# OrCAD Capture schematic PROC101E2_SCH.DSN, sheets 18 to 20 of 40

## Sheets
18 27. HSE CONNECTOR: size C; title: HSE CONNECTOR
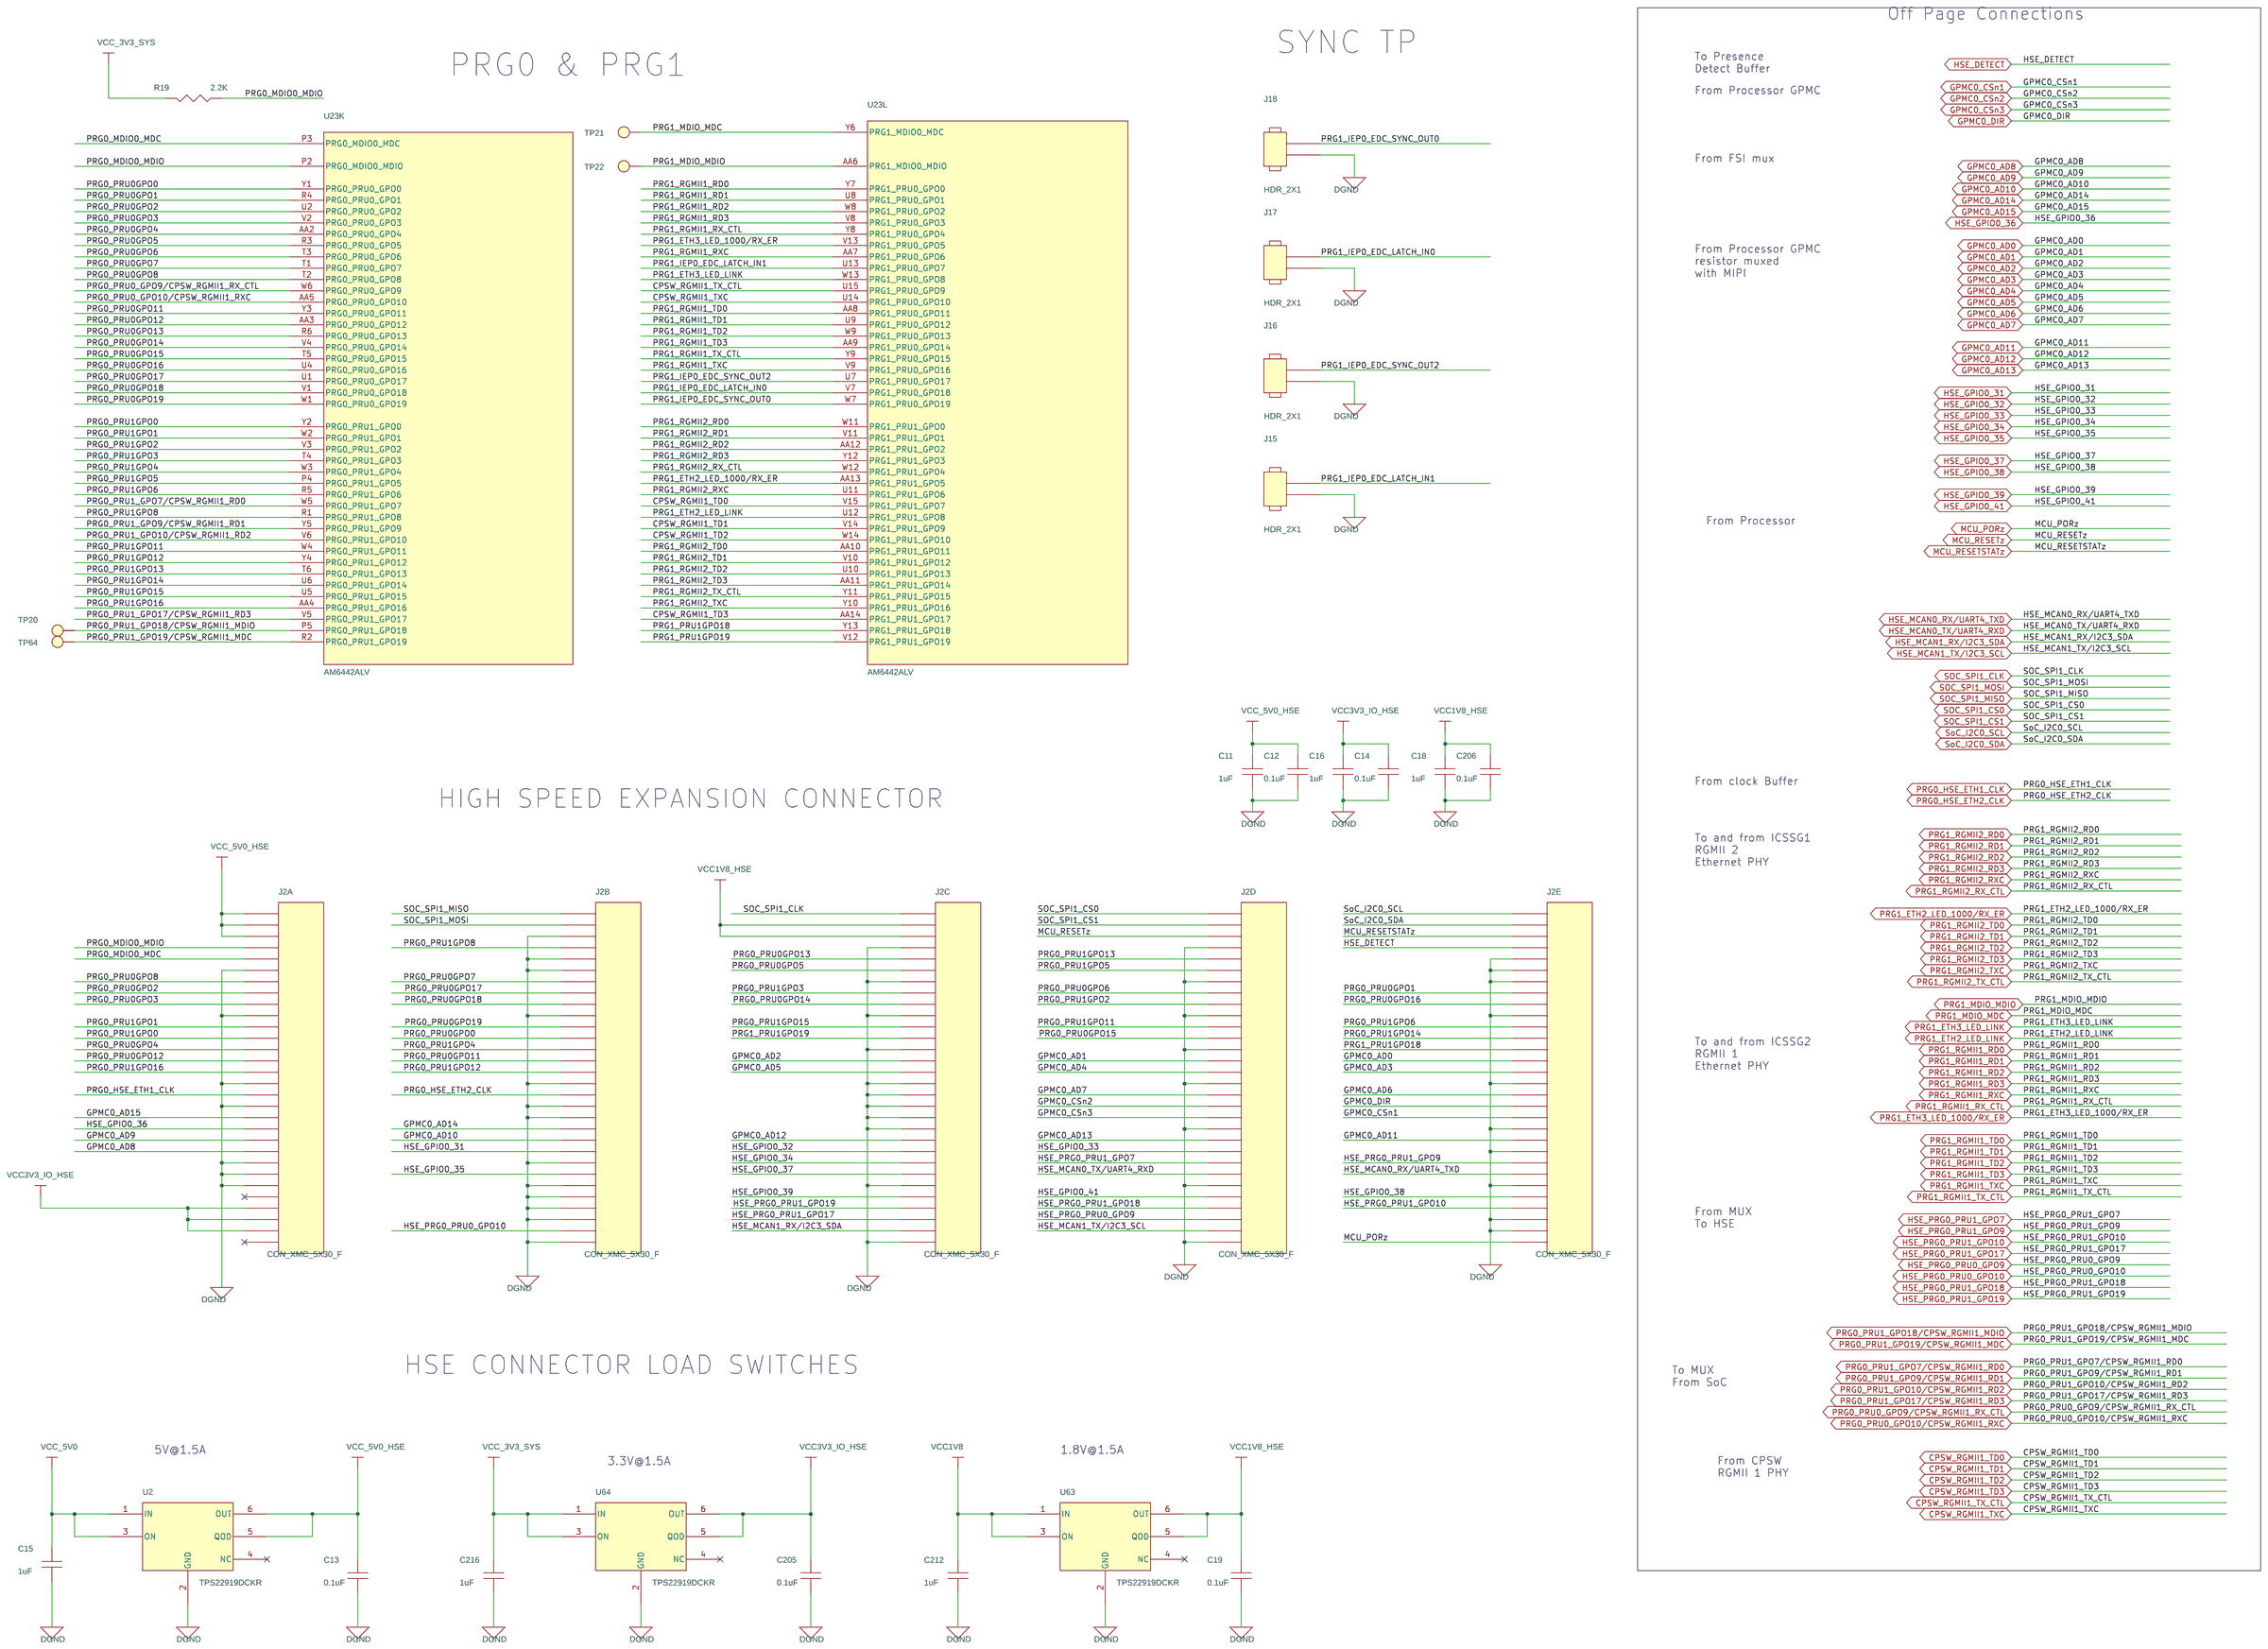
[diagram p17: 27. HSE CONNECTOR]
19 28.GPMC & FSI CONNECTOR: size C; title: GPMC
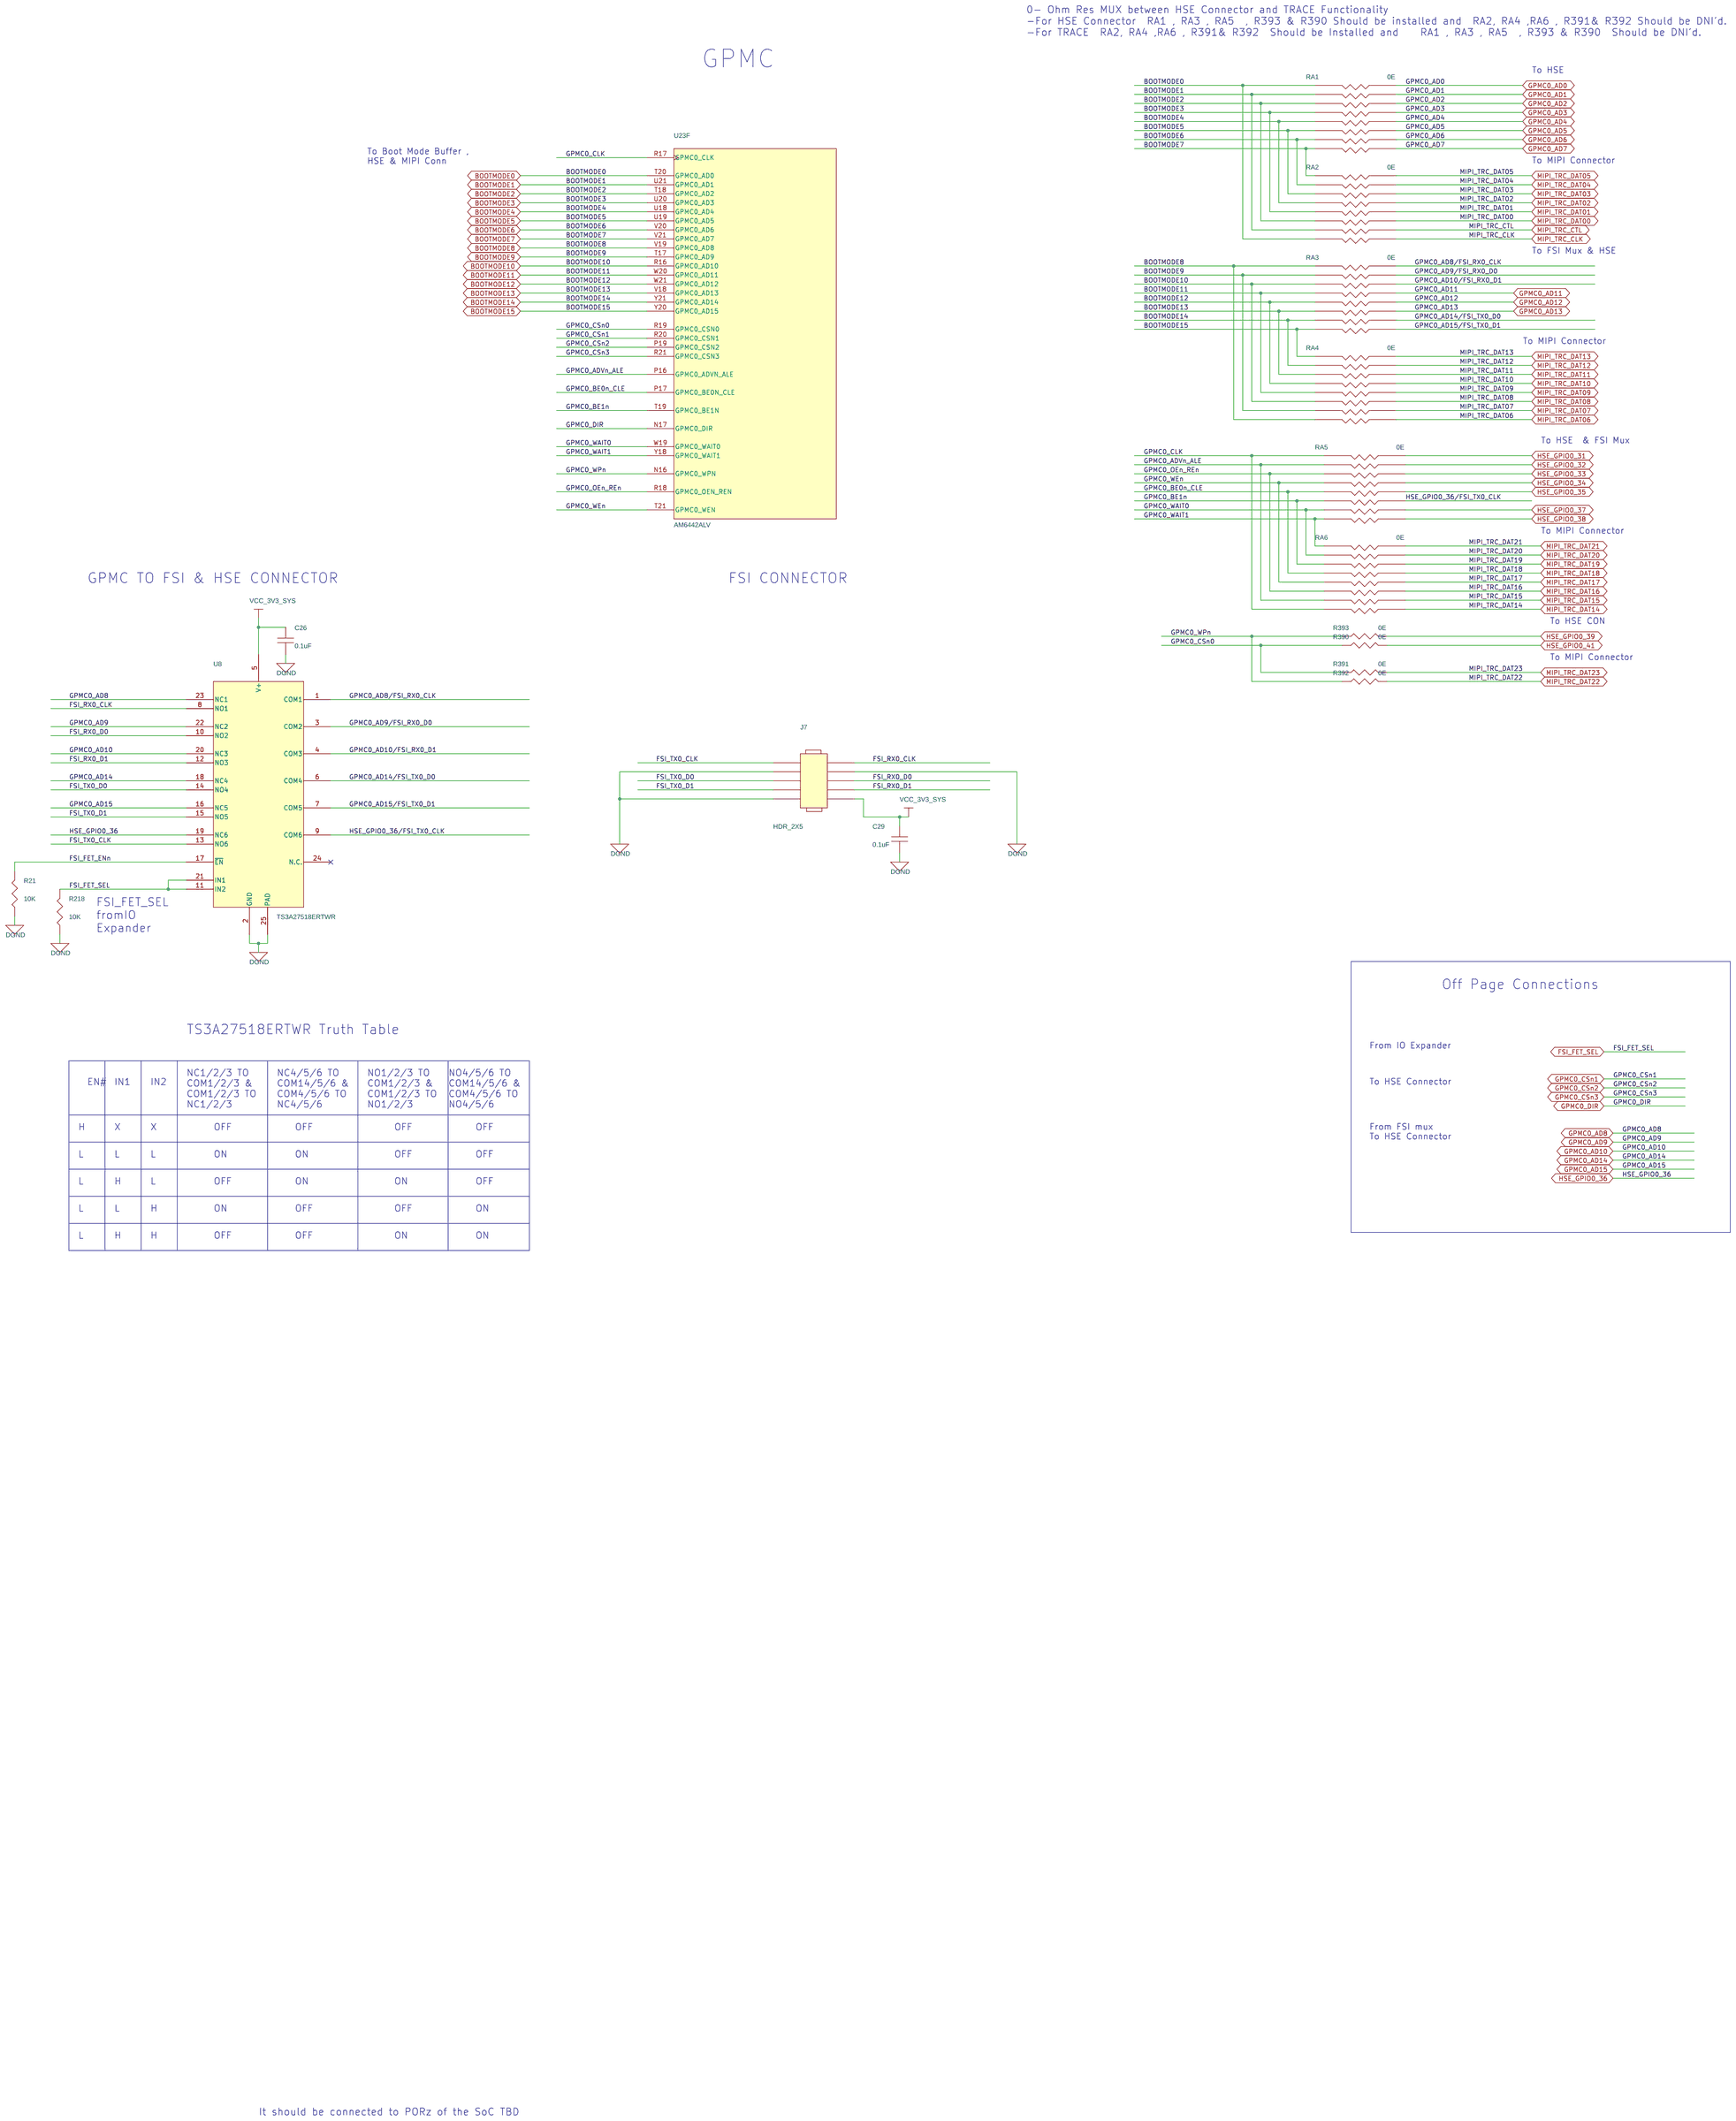
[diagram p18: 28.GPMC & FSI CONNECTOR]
20 25.USB2.0 INTERFACE: size C; title: USB 2.0 INTERFACE
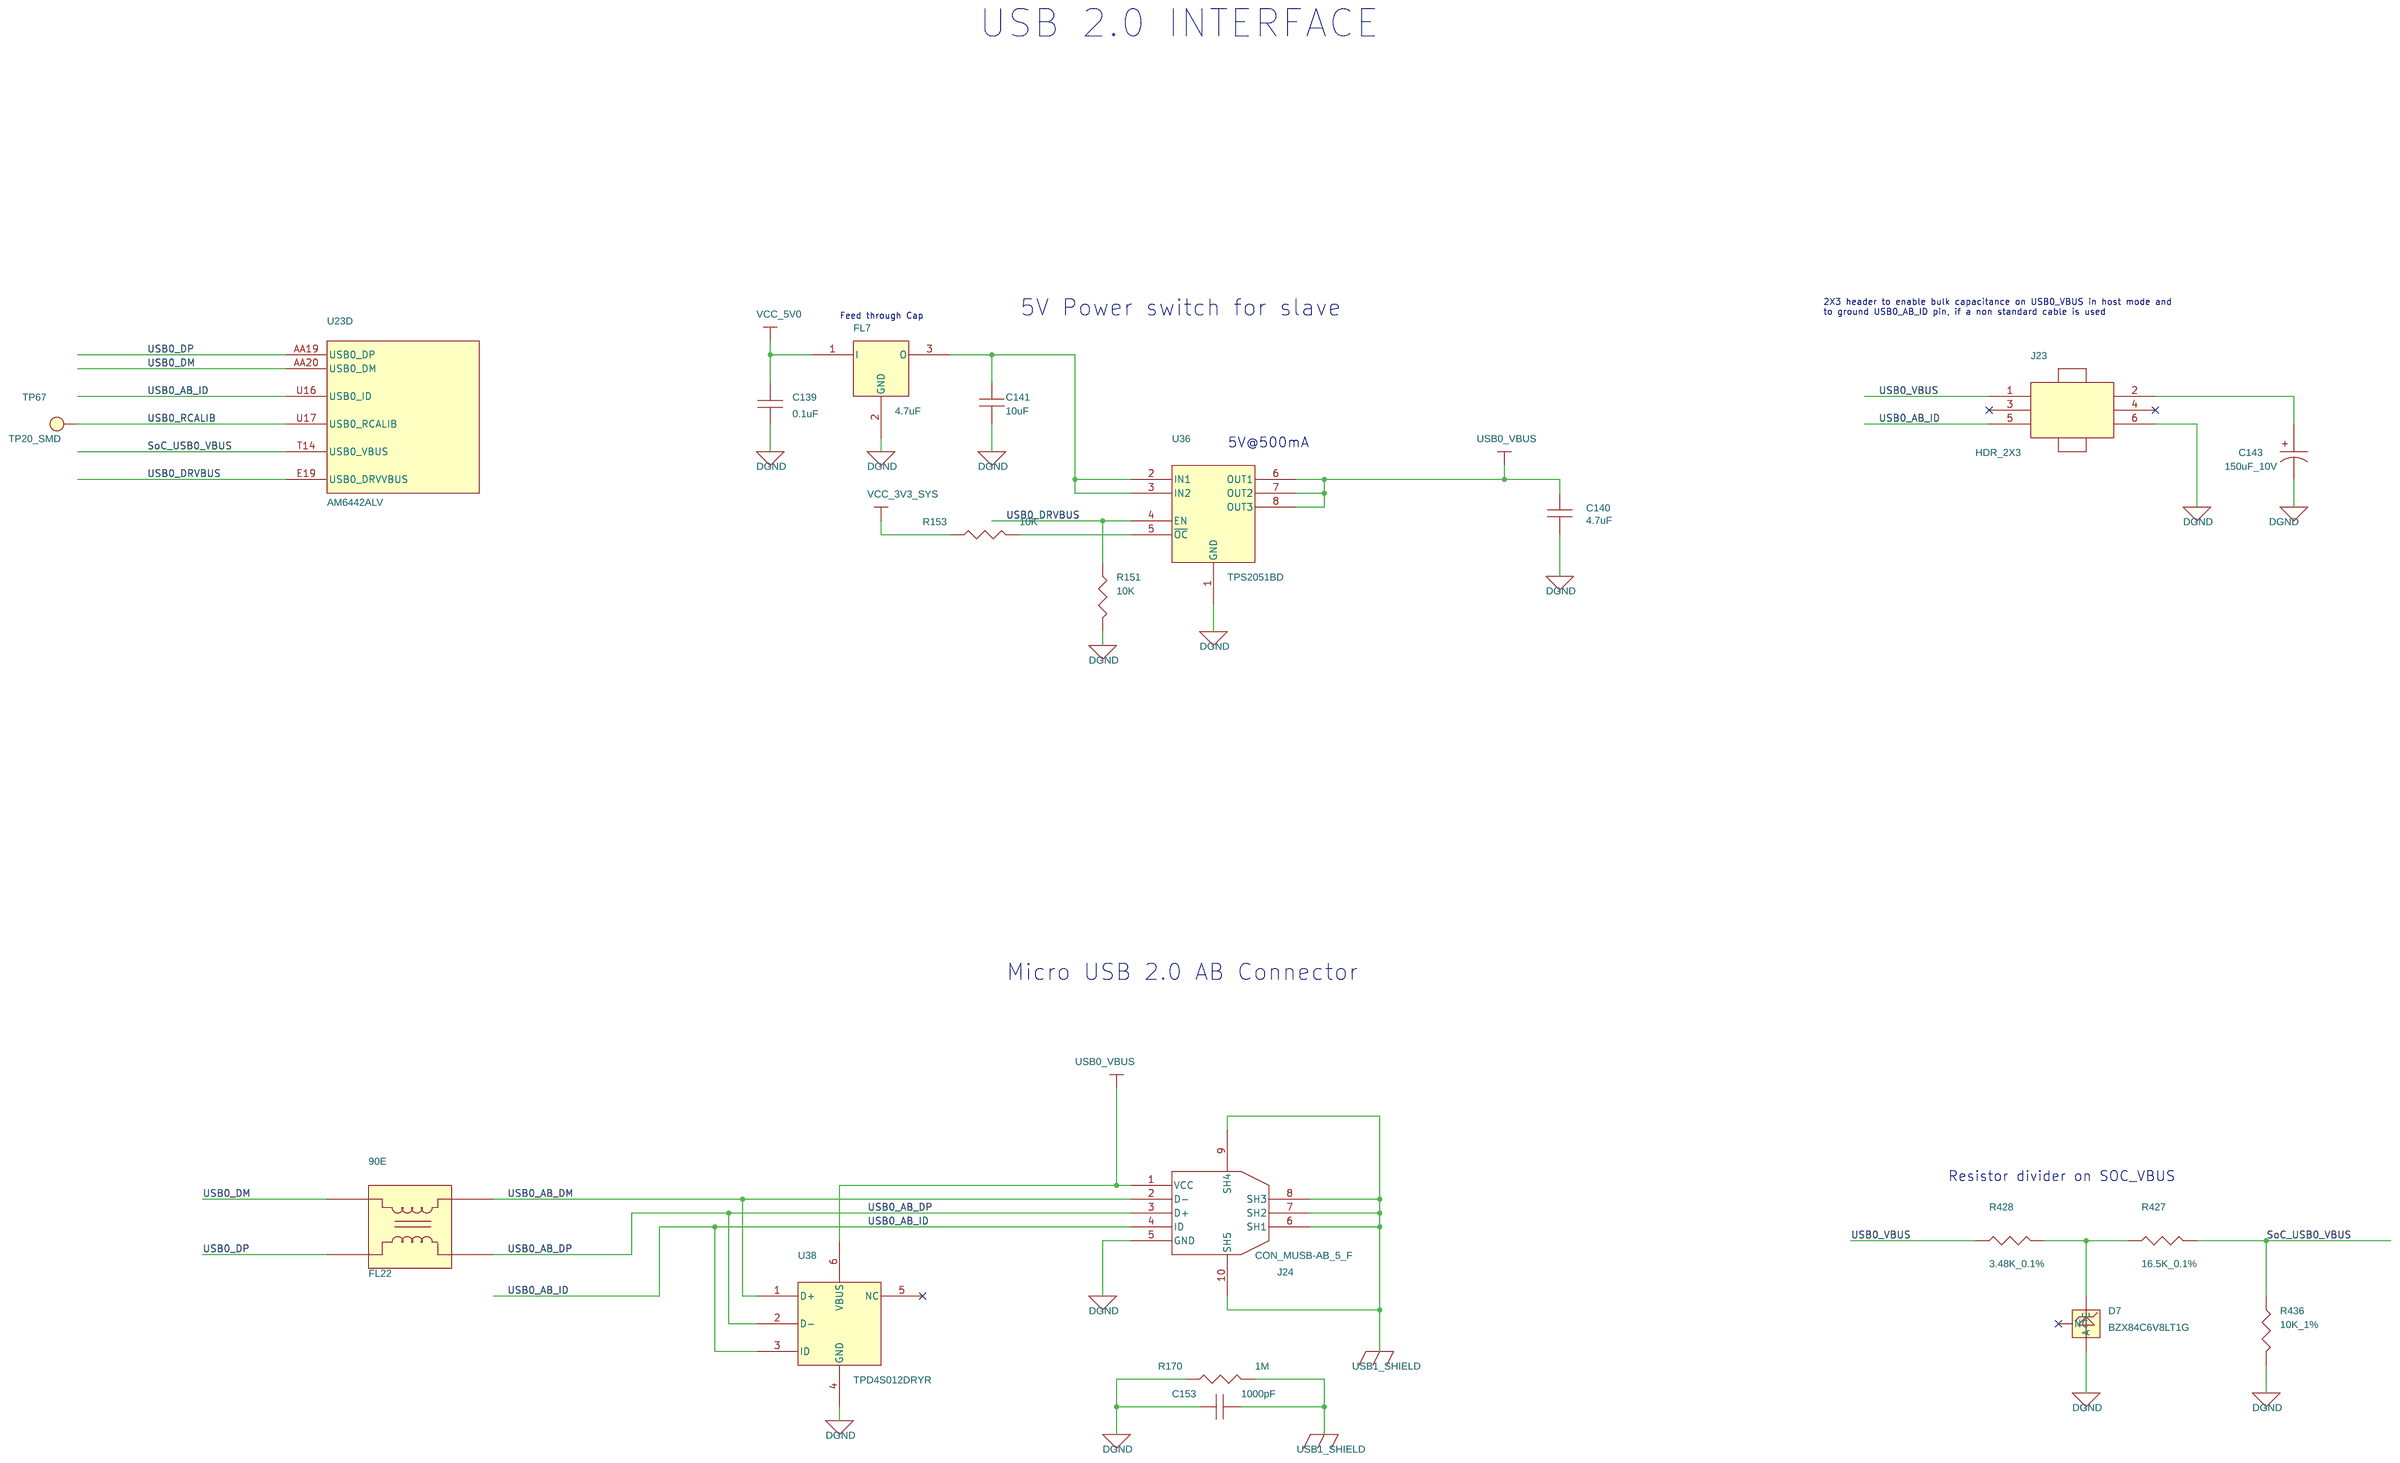
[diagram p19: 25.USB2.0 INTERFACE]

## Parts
sheet 11.SOC VSS
U23  AM6442ALV  [FCBGA441_31-49_680X680_2-6]  (sections A,B,C,D,E,F,G,H,I,J,K,L,M,N,O,P)
sheet 25.USB2.0 INTERFACE
C139  0.1uF  [CAP0402_0-75]
C140  4.7uF  [CAP0402_0-75]
C141  10uF  [CAP0402_0-75]
C143  150uF_10V  [CAPT7343D_3-25]
C153  1000pF  [CAP1206_1-75]
D7  BZX84C6V8LT1G  [SOT23-123_1-2]
FL7  4.7uF  [EMIFIL_NFM21P_0805_1]
FL22  90E  [IND4_ACM2012_90X50_SMD_1-3]
J23  HDR_2X3  [HDR_2X3_TSW-103-07-D_S_T_8-4]
J24  CON_MUSB-AB_5_F  [CON_USBAB5_ZX62RD-AB-5P8_S_R_S_3-2]
R151  10K  [RES0402_0-5]
R153  10K  [RES0402_0-5]
R170  1M  [RES0603_0-75]
R427  16.5K_0.1%  [RES0402_0-5]
R428  3.48K_0.1%  [RES0402_0-5]
R436  10K_1%  [RES0402_0-5]
TP67  TP20_SMD  [TP20_SMD]
U36  TPS2051BD  [SOIC8_1-8]
U38  TPD4S012DRYR  [SON6_SN74LVC2G17_40X60_0-6]
sheet 27. HSE CONNECTOR
C11  1uF  [CAP0402_0-75]
C12  0.1uF  [CAP0402_0-75]
C13  0.1uF  [CAP0402_0-75]
C14  0.1uF  [CAP0402_0-75]
C15  1uF  [CAP0402_0-75]
C16  1uF  [CAP0402_0-75]
C18  1uF  [CAP0402_0-75]
C19  0.1uF  [CAP0402_0-75]
C205  0.1uF  [CAP0402_0-75]
C206  0.1uF  [CAP0402_0-75]
C212  1uF  [CAP0402_0-75]
C216  1uF  [CAP0402_0-75]
J2  CON_XMC_5X30_F  [CON_XMC5X30_SEAF-30-06-05-2-A_S_S_S_6-4]  (sections A,B,C,D,E)
J15  HDR_2X1  [HDR_2X1_100_S_T]
J16  HDR_2X1  [HDR_2X1_100_S_T]
J17  HDR_2X1  [HDR_2X1_100_S_T]
J18  HDR_2X1  [HDR_2X1_100_S_T]
R19  2.2K  [RES0402_0-5]
TP20  TP20_SMD  [TP20_SMD]
TP21  TP20_SMD  [TP20_SMD]
TP22  TP20_SMD  [TP20_SMD]
TP64  TP20_SMD  [TP20_SMD]
U2  TPS22919DCKR  [SC70-6_1-1]
U63  TPS22919DCKR  [SC70-6_1-1]
U64  TPS22919DCKR  [SC70-6_1-1]
sheet 28.GPMC & FSI CONNECTOR
C26  0.1uF  [CAP0402_0-75]
C29  0.1uF  [CAP0402_0-75]
J7  HDR_2X5  [HDR_5X2_100_S_T_8-6]
R21  10K  [RES0402_0-5]
R218  10K  [RES0402_0-5]
R390  0E  [RES0402_0-5]
R391  0E  [RES0402_0-5]
R392  0E  [RES0402_0-5]
R393  0E  [RES0402_0-5]
RA1  0E  [RESA_EXB2HV_0602-8_0-6]
RA2  0E  [RESA_EXB2HV_0602-8_0-6]
RA3  0E  [RESA_EXB2HV_0602-8_0-6]
RA4  0E  [RESA_EXB2HV_0602-8_0-6]
RA5  0E  [RESA_EXB2HV_0602-8_0-6]
RA6  0E  [RESA_EXB2HV_0602-8_0-6]
U8  TS3A27518ERTWR  [QFN24_19-68_160X160_0-8]

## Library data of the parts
U23 = AM64-SVB_BGA441: IC AM64 SoC MICROPROCESSOR BGA441; Chkd/date: MANIRAJA/020520; Crtd /date: ALVY/090420; Custom_Duty: 15%; Customs_HS_Code: 85423100; Distributor_name: NA; Distributor_part_number: NA; Footprint Path: Y:\MIS_DATABASE\Library\ALTIUM_TOOL\PCB_FOOTPRINTS\Altium_Footprint_Lib.PcbLib; Height: 2.57MM; Library Path: Y:\MIS_DATABASE\Library\ALTIUM_TOOL\SCHEMATICS_PARTS\MS_MICROPROCESSOR_Library.schlib; Mfr_name: TEXAS INSTRUMENTS; Mfr_part_number: AM6442ASFGGAALV; Mistral Part No: 141220040002; Package: BGA441; Part_type: ICS\DIGITAL\MICROPROCESSOR; Project: AM64x_SVB BRD; RoHS: NA; Temperature: NA; Tolerance: NA; Voltage: NA; Wattage: NA; Weight: NA; Datasheet: Y:\MIS_DATABASE\DATASHEETS\ICS\DIGITAL\MICROCONTROLLER\AM64-SoC_SVB.PDF
C12-C14 C19 C26 C29 C139 C205 C206 = CAP: CAP CERAMIC 0.1uF 25V 20% X5R 0402; Alt_Mfr_name: YAGEO AMERICA; Alt_Mfr_part_number: CC0402KRX5R8BB104; Chkd/date: MANIRAJA/170820; Crtd /date: ALVY/170820; Custom_Duty: 15%; Customs_HS_Code: 85322990; Distributor_name: DIGIKEY; Distributor_part_number: 732-7495-1-ND; Footprint Path: Y:\MIS_DATABASE\Library\ALTIUM_TOOL\PCB_FOOTPRINTS\Altium_Footprint_Lib.PcbLib; Height: 0.55MM; Library Path: Y:\MIS_DATABASE\Library\ALTIUM_TOOL\SCHEMATICS_PARTS\MS_DISCRETE_Library.schlib; Mfr_name: WURTH ELECTRONICS; Mfr_part_number: 885012105018; Mistral Part No: 120020080003-R; Package: 0402; Part_type: CAPACITORS\CERAMIC; Project: AM64x_EVM_BRD; RoHS: RoHS; Temperature: -55°C+85°C; Tolerance: 20%; Voltage: 25V; Wattage: NA; Weight: 0.65mg; Datasheet: Y:\MIS_DATABASE\DATASHEETS\CAPACITORS\885012105018.PDF
C140 = CAP: CAP CERAMIC 4.7uF 10V 20% X5R 0402; Chkd/date: MANIRAJA/230118; Crtd /date: MANIRAJA/230118; Custom_Duty: 15%; Customs_HS_Code: 85322990; Distributor_name: DIGIKEY; Distributor_part_number: 478-10791-1-ND; Footprint Path: Y:\MIS_DATABASE\Library\ALTIUM_TOOL\PCB_FOOTPRINTS\Altium_Footprint_Lib.PcbLib; Height: 0.71MM; Library Path: Y:\MIS_DATABASE\Library\ALTIUM_TOOL\SCHEMATICS_PARTS\MS_DISCRETE_Library.schlib; Mfr_name: AVX CORPORATION; Mfr_part_number: 0402ZD475MAT2A; Mistral Part No: 120012060002-R; Package: 0402; Part_type: CAPACITORS\CERAMIC; Project: TI_MAXIE_CPB; RoHS: RoHS; Temperature: -55°C+85°C; Tolerance: 20%; Voltage: 10V; Wattage: NA; Weight: 0.65mg; Datasheet: Y:\MIS_DATABASE\DATASHEETS\CAPACITORS\AVX_MLC.PDF
C141 = CAP: CAP CERAMIC 10uF 10V 20% X5R 0402; Chkd/date: MANIRAJA/300520; Crtd /date: ALVY/260520; Custom_Duty: 15%; Customs_HS_Code: 85322990; Distributor_name: DIGIKEY; Distributor_part_number: 490-GRM155R61A106ME11DTR-ND; Footprint Path: Y:\MIS_DATABASE\Library\ALTIUM_TOOL\PCB_FOOTPRINTS\Altium_Footprint_Lib.PcbLib; Height: 0.55MM; Library Path: Y:\MIS_DATABASE\Library\ALTIUM_TOOL\SCHEMATICS_PARTS\MS_DISCRETE_Library.schlib; Mfr_name: MURATA; Mfr_part_number: GRM155R61A106ME11D; Mistral Part No: 120013110019-R; Package: 0402; Part_type: CAPACITORS\CERAMIC; Project: QCS610_NANOSOM; RoHS: RoHS; Temperature: -55°C+85°C; Tolerance: 20%; Voltage: 10V; Wattage: NA; Weight: 3.1mg; Datasheet: Y:\MIS_DATABASE\DATASHEETS\CAPACITORS\MURATA-GXX-SER_NOV17.PDF
C143 = CAP_POL: CAP TANTALUM 150uF 10V 10% ESR 0.9E D7343; Chkd/date: MANIRAJA/240118; Crtd /date: MANIRAJA/240118; Custom_Duty: 15%; Customs_HS_Code: 85322990; Distributor_name: DIGIKEY; Distributor_part_number: 478-11241-1-ND; Footprint Path: Y:\MIS_DATABASE\Library\ALTIUM_TOOL\PCB_FOOTPRINTS\Altium_Footprint_Lib.PcbLib; Height: 3.10MM; Library Path: Y:\MIS_DATABASE\Library\ALTIUM_TOOL\SCHEMATICS_PARTS\MS_DISCRETE_Library.schlib; Mfr_name: AVX CORPORATION; Mfr_part_number: TAJD157K010TNJV; Mistral Part No: 120018010025-R; Package: D7343; Part_type: CAPACITORS\TANTALUM; Project: TI_MAXIE_CPB; RoHS: RoHS; Temperature: -55°C+125°C; Tolerance: 10%; Voltage: 10V; Wattage: NA; Weight: 670mg; Datasheet: Y:\MIS_DATABASE\DATASHEETS\CAPACITORS\AVX-TAJ-SER.PDF
C153 = CAP: CAP CERAMIC 1000pF 2KV 10% X7R 1206; Chkd/date: SHREESHAIL/291106; Crtd /date: MAZHAR/281106; Custom_Duty: 15%; Customs_HS_Code: 85322990; Distributor_name: DIGIKEY; Distributor_part_number: 478-2956-1-ND; Footprint Path: Y:\MIS_DATABASE\Library\ALTIUM_TOOL\PCB_FOOTPRINTS\Altium_Footprint_Lib.PcbLib; Height: 1.52MM; Library Path: Y:\MIS_DATABASE\Library\ALTIUM_TOOL\SCHEMATICS_PARTS\MS_DISCRETE_Library.schlib; Mfr_name: AVX CORPORATION; Mfr_part_number: 1206GC102KAT1A; Mistral Part No: 120015080006-R; Package: 1206; Part_type: CAPACITORS\CERAMIC; Project: ADR1B; RoHS: RoHS; Temperature: -55°C+125°C; Tolerance: 10%; Voltage: 2KV; Wattage: NA; Weight: 16.2mg; Datasheet: Y:\MIS_DATABASE\DATASHEETS\CAPACITORS\AVX_HV-MLC.PDF
D7 = DIODE_ZENER_SOT23_13: DIODE ZENER 250mW 6.8V SOT23-123; Chkd/date: MANIRAJA/031017; Crtd /date: MANIRAJA/031017; Custom_Duty: 15%; Customs_HS_Code: 85412900; Distributor_name: DIGIKEY; Distributor_part_number: BZX84C6V8LT1GOSCT-ND; Height: 1.11MM; Mfr_name: ON SEMICONDUCTOR; Mistral Part No: 130017100002-R; Package: SOT23-123; Part_type: DIODE\ZENER; Project: TI_MAXIE_CPB; RoHS: RoHS; Temperature: -65°C+150°C; Tolerance: NA; Voltage: 6.8V; Wattage: NA; Weight: 8mg; Datasheet: Y:\MIS_DATABASE\DATASHEETS\DISCRETES\DIODES\BZX84XX.PDF
FL7 = EMI_FILTER: PASSIVE FILTER EMI 4.7uF 0805-3; Chkd/date: VASANTHA/191216; Crtd /date: USMAN/200409; Custom_Duty: 24%; Customs_HS_Code: 85437099; Distributor_name: NA; Distributor_part_number: NA; Height: 0.95MM; Mfr_name: MURATA; Mfr_part_number: NFM21PC475B1A3; Mistral Part No: 130009060011; Package: 0805; Part_type: FILTER; Project: AXON; Temperature: -40°C+85°C; Tolerance: NA; Voltage: NA; Wattage: NA; Weight: NA; Datasheet: Y:\MIS_DATABASE\DATASHEETS\DISCRETES\INDUCTORS\NFM21P.PDF
FL22 = EMIFILTER_ACM: PASSIVE FILTER COMMON MODE 90E 400mA SMD; Chkd/date: MANIRAJA/130218; Crtd /date: MAZHAR/270907; Custom_Duty: 24%; Customs_HS_Code: 85437099; Distributor_name: DIGIKEY; Distributor_part_number: 445-2207-1-ND; Height: 1.30MM; Mfr_name: TDK CORPORATION; Mfr_part_number: ACM2012-900-2P-T002; Mistral Part No: 130009030803-R; Package: SMD; Part_type: FILTER; Project: SMART VIEW_NVR; RoHS: RoHS; Temperature: -40°C+85°C; Tolerance: NA; Voltage: NA; Wattage: NA; Weight: 5.5mg; Datasheet: Y:\MIS_DATABASE\DATASHEETS\ICS\MISC\ACM2012-SER.PDF
J23 = HEADER_3X2: CON HDR 2X3 2.54MM PITCH ST TH; Chkd/date: MANIRAJA/230118; Crtd /date: MANIRAJA/220118; Custom_Duty: 24%; Customs_HS_Code: 85369090; Distributor_name: DIGIKEY; Distributor_part_number: SAM1034-03-ND; Height: 8.38MM; Mfr_name: SAMTEC; Mfr_part_number: TSW-103-07-T-D; Mistral Part No: 150018010019-R; Package: THRU-HOLE; Part_type: CONNECTOR\HEADERS; Project: TI_MAXIE_CPB; RoHS: RoHS; Temperature: -55°C+105°C; Tolerance: NA; Voltage: NA; Wattage: NA; Weight: NA; Datasheet: Y:\MIS_DATABASE\DATASHEETS\CONNECTORS\TSW-MK.PDF
J24 = CON_USB_MINI-AB_10: CON MICRO USB-AB TYPE 5POS FEMALE RT SMD; Chkd/date: MANIRAJA/150620; Crtd /date: MUDDU/090410; Custom_Duty: 24%; Customs_HS_Code: 85369090; Distributor_name: DIGIKEY; Distributor_part_number: H125777CT-ND; Footprint Path: Y:\MIS_DATABASE\Library\ALTIUM_TOOL\PCB_FOOTPRINTS\Altium_Footprint_Lib.PcbLib; Height: 3.15MM; Library Path: Y:\MIS_DATABASE\Library\ALTIUM_TOOL\SCHEMATICS_PARTS\MS_CONNECTOR_Library.schlib; Mfr_name: HRS; Mfr_part_number: ZX62RD-AB-5P8(30); Mistral Part No: 150010040003-R; Package: SMD; Part_type: CONNECTOR\USB; Project: ESEE; RoHS: RoHS; Temperature: -30°C+85°C; Tolerance: NA; Voltage: NA; Wattage: NA; Weight: NA; Datasheet: Y:\MIS_DATABASE\DATASHEETS\CONNECTORS\ZX62RD-AB-5P8.PDF
R21 R151 R153 R218 = RESISTOR: RES 10K 1/16W 5% 0402; Chkd/date: VASANTHA/061216; Crtd /date: MAZHAR/230805; Custom_Duty: 15%; Customs_HS_Code: 85332119; Distributor_name: DIGIKEY; Distributor_part_number: 311-10KJRCT-ND; Footprint Path: Y:\MIS_DATABASE\Library\ALTIUM_TOOL\PCB_FOOTPRINTS\Altium_Footprint_Lib.PcbLib; Height: 0.40MM; Library Path: Y:\MIS_DATABASE\Library\ALTIUM_TOOL\SCHEMATICS_PARTS\MS_DISCRETE_Library.schlib; Mfr_name: YAGEO AMERICA; Mfr_part_number: RC0402JR-0710KL; Mistral Part No: 110011060021-R; Package: 0402; Part_type: RESISTORS\FIXED; Project: HSE; RoHS: RoHS; Temperature: -55°C+155°C; Tolerance: 5%; Voltage: NA; Wattage: 1/16W; Weight: 0.65mg; Datasheet: Y:\MIS_DATABASE\DATASHEETS\RESISTORS\RCXXXXL-SER_MAR18.PDF
R170 = RESISTOR: RES 1M 1/10W 5% 0603; Chkd/date: VASANTHA/060217; Crtd /date: USMAN/111207; Custom_Duty: 15%; Customs_HS_Code: 85332119; Distributor_name: DIGIKEY; Distributor_part_number: P1.0MGCT-ND; Footprint Path: Y:\MIS_DATABASE\Library\ALTIUM_TOOL\PCB_FOOTPRINTS\Altium_Footprint_Lib.PcbLib; Height: 0.55MM; Library Path: Y:\MIS_DATABASE\Library\ALTIUM_TOOL\SCHEMATICS_PARTS\MS_DISCRETE_Library.schlib; Mfr_name: PANASONIC-ECG; Mfr_part_number: ERJ-3GEYJ105V; Mistral Part No: 110009030413-R; Package: 0603; Part_type: RESISTORS\FIXED; Project: BSN; RoHS: RoHS; Temperature: -55°C+155°C; Tolerance: 5%; Voltage: NA; Wattage: 1/10W; Weight: 2mg; Datasheet: Y:\MIS_DATABASE\DATASHEETS\RESISTORS\PAN-ERJSER_NOV17.PDF
R427 = RESISTOR: RES 16.5K 1/16W 0.1% 0402; Chkd/date: MANIRAJA/051018; Crtd /date: ALVY/051018; Custom_Duty: 15%; Customs_HS_Code: 85332119; Distributor_name: DIGIKEY; Distributor_part_number: P16.5KDCCT-ND; Footprint Path: Y:\MIS_DATABASE\Library\ALTIUM_TOOL\PCB_FOOTPRINTS\Altium_Footprint_Lib.PcbLib; Height: 0.40MM; Library Path: Y:\MIS_DATABASE\Library\ALTIUM_TOOL\SCHEMATICS_PARTS\MS_DISCRETE_Library.schlib; Mfr_name: PANASONIC-ECG; Mfr_part_number: ERA-2AEB1652X; Mistral Part No: 110018100006-R; Package: 0402; Part_type: RESISTORS\FIXED; Project: TI_J7_SVB-DUT; RoHS: RoHS; Temperature: -55°C+155°C; Tolerance: 0.1%; Voltage: NA; Wattage: 1/16W; Weight: 0.6mg; Datasheet: Y:\MIS_DATABASE\DATASHEETS\RESISTORS\ERA-1A.PDF
R428 = RESISTOR: RES 3.48K 1/16W 0.1% 0402; Chkd/date: MANIRAJA/051018; Crtd /date: ALVY/051018; Custom_Duty: 15%; Customs_HS_Code: 85332119; Distributor_name: DIGIKEY; Distributor_part_number: P3.48KDCCT-ND; Footprint Path: Y:\MIS_DATABASE\Library\ALTIUM_TOOL\PCB_FOOTPRINTS\Altium_Footprint_Lib.PcbLib; Height: 0.40MM; Library Path: Y:\MIS_DATABASE\Library\ALTIUM_TOOL\SCHEMATICS_PARTS\MS_DISCRETE_Library.schlib; Mfr_name: PANASONIC-ECG; Mfr_part_number: ERA-2AEB3481X; Mistral Part No: 110018100005-R; Package: 0402; Part_type: RESISTORS\FIXED; Project: TI_J7_SVB-DUT; RoHS: RoHS; Temperature: -55°C+155°C; Tolerance: 0.1%; Voltage: NA; Wattage: 1/16W; Weight: 0.6mg; Datasheet: Y:\MIS_DATABASE\DATASHEETS\RESISTORS\ERA-1A.PDF
R436 = RESISTOR: RES 10K 1/16W 1% 0402; Chkd/date: VASANTHA/201216; Crtd /date: GEETHA/290506; Custom_Duty: 15%; Customs_HS_Code: 85332119; Distributor_name: DIGIKEY; Distributor_part_number: 311-10.0KLRTR-ND; Footprint Path: Y:\MIS_DATABASE\Library\ALTIUM_TOOL\PCB_FOOTPRINTS\Altium_Footprint_Lib.PcbLib; Height: 0.40MM; Library Path: Y:\MIS_DATABASE\Library\ALTIUM_TOOL\SCHEMATICS_PARTS\MS_DISCRETE_Library.schlib; Mfr_name: YAGEO AMERICA; Mfr_part_number: RC0402FR-0710KL; Mistral Part No: 110015090015-R; Package: 0402; Part_type: RESISTORS\FIXED; Project: VOCERA; RoHS: RoHS; Temperature: -55°C+155°C; Tolerance: 1%; Voltage: NA; Wattage: 1/16W; Weight: 0.65mg; Datasheet: Y:\MIS_DATABASE\DATASHEETS\RESISTORS\RCXXXXL-SER_MAR18.PDF
TP20-TP22 TP64 TP67 = TESTPOINT: TESTPOINT CIR 20 SMD; Chkd/date: SHREESHAIL/171006; Crtd /date: MAZHAR/171006; Custom_Duty: NA; Customs_HS_Code: NA; Distributor_name: NA; Distributor_part_number: NA; Footprint Path: Y:\MIS_DATABASE\Library\ALTIUM_TOOL\PCB_FOOTPRINTS\Altium_Footprint_Lib.PcbLib; Height: NA; Library Path: Y:\MIS_DATABASE\Library\ALTIUM_TOOL\SCHEMATICS_PARTS\MS_DISCRETE_Library.schlib; MECHANICAL 3D STEP FILE: NA; Mfr_name: LOCAL; Mistral Part No: NA; Package: SMD; Project: BT MODULE_CSRBC04; RoHS: NA; Temperature: NA; Tolerance: NA; Voltage: NA; Wattage: NA; Weight: NA; Datasheet: NA
U36 = TPS2051BD_SOIC8: IC POWER DISTRIBUTION SWITCH SOIC8; Chkd/date: NAVEED/150714; Crtd /date: VASANTHA/190614; Custom_Duty: 15%; Customs_HS_Code: 85423100; Distributor_name: DIGIKEY; Distributor_part_number: 296-26911-5-ND; Footprint Path: Y:\MIS_DATABASE\Library\ALTIUM_TOOL\PCB_FOOTPRINTS\Altium_Footprint_Lib.PcbLib; Height: 1.75MM; Library Path: Y:\MIS_DATABASE\Library\ALTIUM_TOOL\SCHEMATICS_PARTS\MS_MISCPOWER_Library.schlib; Mfr_name: TEXAS INSTRUMENTS; Mistral Part No: 142014060011-R; Package: SOIC8; Part_type: ICS\POWER; Project: AEGIS_POM; RoHS: RoHS; Temperature: -40°C+125°C; Tolerance: NA; Voltage: NA; Wattage: NA; Weight: 72.6mg; Datasheet: Y:\MIS_DATABASE\DATASHEETS\MISC\REGULATORS\TPS2051BDBVR.PDF
U38 = TPD4S012DRY_SON6: IC 4CH ESD SOLUTION FOR USB-HS/USB OTG/USB CHARGER INTERFACE SON6; Chkd/date: MANIRAJA/040719; Crtd /date: BAVISH/190811; Custom_Duty: 15%; Customs_HS_Code: 85423100; Distributor_name: DIGIKEY; Distributor_part_number: 296-24244-1-ND; Footprint Path: Y:\MIS_DATABASE\Library\ALTIUM_TOOL\PCB_FOOTPRINTS\Altium_Footprint_Lib.PcbLib; Height: 0.60MM; Library Path: Y:\MIS_DATABASE\Library\ALTIUM_TOOL\SCHEMATICS_PARTS\MS_MISCINTERFACE_Library.schlib; Mfr_name: TEXAS INSTRUMENTS; Mistral Part No: 141011080022-R; Package: SON6; Part_type: ICS\INTERFACE; Project: ACRO_DM3730; RoHS: RoHS; Temperature: -40°C+85°C; Tolerance: NA; Voltage: NA; Wattage: NA; Weight: 3.2mg; Datasheet: Y:\MIS_DATABASE\DATASHEETS\ICS\INTERFACE\TPD4S012DRYR.PDF
C11 C15 C16 C18 C212 C216 = CAP: CAP CERAMIC 1uF 10V 20% X5R 0402; Chkd/date: MANIRAJA/210820; Crtd /date: ALVY/190820; Custom_Duty: 15%; Customs_HS_Code: 85322990; Distributor_name: DIGIKEY; Distributor_part_number: 732-7489-1-ND; Footprint Path: Y:\MIS_DATABASE\Library\ALTIUM_TOOL\PCB_FOOTPRINTS\Altium_Footprint_Lib.PcbLib; Height: 0.55MM; Library Path: Y:\MIS_DATABASE\Library\ALTIUM_TOOL\SCHEMATICS_PARTS\MS_DISCRETE_Library.schlib; Mfr_name: WURTH ELECTRONICS; Mfr_part_number: 885012105012; Mistral Part No: 120020080009-R; Package: 0402; Part_type: CAPACITORS\CERAMIC; Project: AM64x_EVM_BRD; RoHS: RoHS; Temperature: -55°C+85°C; Tolerance: 20%; Voltage: 10V; Wattage: NA; Weight: 0.65mg; Datasheet: Y:\MIS_DATABASE\DATASHEETS\CAPACITORS\885012105012.PDF
J2 = CON_XMC30X5_F_SEAF: CON XMC 5X30 1.27MM PITCH FEMALE ST SMD; Chkd/date: MANIRAJA/190620; Crtd /date: ALVY/190620; Custom_Duty: 24%; Customs_HS_Code: 85369090; Distributor_name: DIGIKEY; Distributor_part_number: SEAF-30-06.0-L-05-2-A-K-TR-ND; Footprint Path: Y:\MIS_DATABASE\Library\ALTIUM_TOOL\PCB_FOOTPRINTS\Altium_Footprint_Lib.PcbLib; Height: 6.34MM; Library Path: Y:\MIS_DATABASE\Library\ALTIUM_TOOL\SCHEMATICS_PARTS\MS_CONNECTOR_Library.schlib; Mfr_name: SAMTEC; Mfr_part_number: SEAF-30-06.0-L-05-2-A-K-TR; Mistral Part No: 150020060030-R; Package: SMD; Part_type: CONNECTOR\XMC; Project: AM64x-GP_EVM BRD; RoHS: RoHS; Temperature: -55°C+125°C; Tolerance: NA; Voltage: NA; Wattage: NA; Weight: NA; Datasheet: Y:\MIS_DATABASE\DATASHEETS\CONNECTORS\SEAF-A-SER.PDF
J15-J18 = HEADER_2X1: CON HDR 2X1 2.54MM PITCH ST TH; Chkd/date: NAVEED/210714; Crtd /date: USMAN/031012; Custom_Duty: 24%; Customs_HS_Code: 85369090; Distributor_name: DIGIKEY; Distributor_part_number: WM8072-ND; Height: 5.60MM; Mfr_name: MOLEX; Mfr_part_number: 90120-0122; Mistral Part No: 150012100005-R; Package: THRU-HOLE; Part_type: CONNECTOR\HEADERS; Project: NPOL_FEP; RoHS: RoHS; Temperature: -55°C+125°C; Tolerance: NA; Voltage: NA; Wattage: NA; Weight: NA; Datasheet: Y:\MIS_DATABASE\DATASHEETS\CONNECTORS\90120-SERIES.PDF
R19 = RESISTOR: RES 2.2K 1/16W 5% 0402; Chkd/date: VASANTHA/061216; Crtd /date: BAVISH/021210; Custom_Duty: 15%; Customs_HS_Code: 85332119; Distributor_name: DIGIKEY; Distributor_part_number: 311-2.2KJRCT-ND; Footprint Path: Y:\MIS_DATABASE\Library\ALTIUM_TOOL\PCB_FOOTPRINTS\Altium_Footprint_Lib.PcbLib; Height: 0.40MM; Library Path: Y:\MIS_DATABASE\Library\ALTIUM_TOOL\SCHEMATICS_PARTS\MS_DISCRETE_Library.schlib; Mfr_name: YAGEO AMERICA; Mfr_part_number: RC0402JR-072K2L; Mistral Part No: 110010120018-R; Package: 0402; Part_type: RESISTORS\FIXED; Project: TE4; RoHS: RoHS; Temperature: -55°C+155°C; Tolerance: 5%; Voltage: NA; Wattage: 1/16W; Weight: 0.65mg; Datasheet: Y:\MIS_DATABASE\DATASHEETS\RESISTORS\RCXXXXL-SER_MAR18.PDF
U2 U63 U64 = TPS22919_SC70-6: IC 5.5V 1.5A 90mE SELF PROTECTED LOAD SWITCH CONTROLLED RISE TIME SC70-6; Chkd/date: MANIRAJA/090519; Crtd /date: ALVY/090519; Custom_Duty: 15%; Customs_HS_Code: 85423100; Distributor_name: MOUSER; Distributor_part_number: 595-TPS22919DCKR; Footprint Path: Y:\MIS_DATABASE\Library\ALTIUM_TOOL\PCB_FOOTPRINTS\Altium_Footprint_Lib.PcbLib; Height: 1.10MM; Library Path: Y:\MIS_DATABASE\Library\ALTIUM_TOOL\SCHEMATICS_PARTS\MS_MISCPOWER_Library.schlib; Mfr_name: TEXAS INSTRUMENTS; Mistral Part No: 142019050003-R; Package: SC70-6; Part_type: ICS\POWER\CONTROL; Project: AM654x SOM_TEST_JIG; RoHS: RoHS; Temperature: -40°C+105°C; Tolerance: NA; Voltage: NA; Wattage: NA; Weight: NA; Datasheet: Y:\MIS_DATABASE\DATASHEETS\ICS\POWER\TPS22919.PDF
J7 = HEADER_5X2: CON HDR 2X5 2.54MM PITCH ST TH; Chkd/date: VASANTHA/220317; Crtd /date: MANIRAJA/210317; Custom_Duty: 24%; Customs_HS_Code: 85369090; Distributor_name: DIGIKEY; Distributor_part_number: 609-3243-ND; Height: 8.58MM; Mfr_name: FCI; Mfr_part_number: 67997-410HLF; Mistral Part No: 150015100040-R; Package: THRU-HOLE; Part_type: CONNECTOR\HEADERS; Project: CYPHY_ROADKILL; RoHS: RoHS; Temperature: NA; Tolerance: NA; Voltage: NA; Wattage: NA; Weight: NA; Datasheet: Y:\MIS_DATABASE\DATASHEETS\CONNECTORS\67997.PDF
R390 R393 = RESISTOR: RES 0E 1/16W JUMPER 0402; Chkd/date: VASANTHA/201216; Crtd /date: MUDDU/190810; Custom_Duty: 15%; Customs_HS_Code: 85332119; Distributor_name: DIGIKEY; Distributor_part_number: 541-0.0JCT-ND; Footprint Path: Y:\MIS_DATABASE\Library\ALTIUM_TOOL\PCB_FOOTPRINTS\Altium_Footprint_Lib.PcbLib; Height: 0.40MM; Library Path: Y:\MIS_DATABASE\Library\ALTIUM_TOOL\SCHEMATICS_PARTS\MS_DISCRETE_Library.schlib; Mfr_name: VISHAY; Mfr_part_number: CRCW04020000Z0ED; Mistral Part No: 110010080019-R; Package: 0402; Part_type: RESISTORS\FIXED; Project: PB_BUGBASE; RoHS: RoHS; SIGNAL_MODEL: RES; Temperature: -55°C+155°C; Tolerance: NA; Voltage: NA; Wattage: 1/16W; Weight: 0.65mg; Datasheet: Y:\MIS_DATABASE\DATASHEETS\RESISTORS\CRCW0603.PDF
R391 R392 = RESISTOR: RES 0E 1/16W JUMPER 0402; Assembly: DNI; Chkd/date: VASANTHA/201216; Crtd /date: MUDDU/190810; Custom_Duty: 15%; Customs_HS_Code: 85332119; Distributor_name: DIGIKEY; Distributor_part_number: 541-0.0JCT-ND; Footprint Path: Y:\MIS_DATABASE\Library\ALTIUM_TOOL\PCB_FOOTPRINTS\Altium_Footprint_Lib.PcbLib; Height: 0.40MM; Library Path: Y:\MIS_DATABASE\Library\ALTIUM_TOOL\SCHEMATICS_PARTS\MS_DISCRETE_Library.schlib; Mfr_name: VISHAY; Mfr_part_number: CRCW04020000Z0ED; Mistral Part No: 110010080019-R; Package: 0402; Part_type: RESISTORS\FIXED; Project: PB_BUGBASE; RoHS: RoHS; SIGNAL_MODEL: RES; Temperature: -55°C+155°C; Tolerance: NA; Voltage: NA; Wattage: 1/16W; Weight: 0.65mg; Datasheet: Y:\MIS_DATABASE\DATASHEETS\RESISTORS\CRCW0603.PDF
RA1 RA3 RA5 = RESARR_ISO8_0402: RES ARRAY 0E 1/16W JUMPER 0602-8; Chkd/date: SHREESHAIL/121205; Crtd /date: MAZHAR/300505; Custom_Duty: 15%; Customs_HS_Code: 85332119; Distributor_name: DIGIKEY; Distributor_part_number: Y1000CT-ND; Footprint Path: Y:\MIS_DATABASE\Library\ALTIUM_TOOL\PCB_FOOTPRINTS\Altium_Footprint_Lib.PcbLib; Height: 0.55MM; Library Path: Y:\MIS_DATABASE\Library\ALTIUM_TOOL\SCHEMATICS_PARTS\MS_DISCRETE_Library.schlib; Mfr_name: PANASONIC-ECG; Mfr_part_number: EXB-2HVR000V; Mistral Part No: 110009030004-R; Package: 0602-8; Part_type: RESISTORS\ARRAY; Project: V12SFP; RoHS: RoHS; SIGNAL_MODEL: RESA; Temperature: -55°C+125°C; Tolerance: NA; Voltage: NA; Wattage: 1/16W; Weight: 9mg; Datasheet: Y:\MIS_DATABASE\DATASHEETS\RESISTORS\EXB-18V.PDF
RA2 RA4 RA6 = RESARR_ISO8_0402: RES ARRAY 0E 1/16W JUMPER 0602-8; Assembly: DNI; Chkd/date: SHREESHAIL/121205; Crtd /date: MAZHAR/300505; Custom_Duty: 15%; Customs_HS_Code: 85332119; Distributor_name: DIGIKEY; Distributor_part_number: Y1000CT-ND; Footprint Path: Y:\MIS_DATABASE\Library\ALTIUM_TOOL\PCB_FOOTPRINTS\Altium_Footprint_Lib.PcbLib; Height: 0.55MM; Library Path: Y:\MIS_DATABASE\Library\ALTIUM_TOOL\SCHEMATICS_PARTS\MS_DISCRETE_Library.schlib; Mfr_name: PANASONIC-ECG; Mfr_part_number: EXB-2HVR000V; Mistral Part No: 110009030004-R; Package: 0602-8; Part_type: RESISTORS\ARRAY; Project: V12SFP; RoHS: RoHS; SIGNAL_MODEL: RESA; Temperature: -55°C+125°C; Tolerance: NA; Voltage: NA; Wattage: 1/16W; Weight: 9mg; Datasheet: Y:\MIS_DATABASE\DATASHEETS\RESISTORS\EXB-18V.PDF
U8 = TS3A27518ERTWR_QFN24: IC 6-BIT 1OF2 MULTIPLEXER/DEMULTIPLEXER WITH ESD & LCCI QFN24; Chkd/date: MANIRAJA/111017; Crtd /date: USMAN/230709; Custom_Duty: 15%; Customs_HS_Code: 85423100; Distributor_name: DIGIKEY; Distributor_part_number: 296-25415-1-ND; Height: 0.80MM; Mfr_name: TEXAS INSTRUMENTS; Mistral Part No: 141009070012-R; Package: QFN24; Part_type: ICS\DIGITAL\COMBINATIONAL; Project: BUG_BASE-II; RoHS: RoHS; Temperature: -40°C+85°C; Tolerance: NA; Voltage: NA; Wattage: NA; Weight: NA; Datasheet: Y:\MIS_DATABASE\DATASHEETS\ICS\DIGITAL\BUSTRANSCEIVER\TS3A27518E.PDF

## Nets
DGND: C11.2 C12.2 C13.2 C14.2 C15.2 C16.2 C18.2 C19.2 C26.2 C29.2 C139.1 C140.2 C141.2 C143.2 C153.1 C205.2 C206.2 C212.2 C216.2 D7.1(A) FL7.2(GND) J2.A6 J2.A10 J2.A16 J2.A18 J2.A23 J2.A24 J2.A25 J2.B3 J2.B5 J2.B6 J2.B10 J2.B16 J2.B18 J2.B19 J2.B23 J2.B25 J2.B26 J2.B27 J2.B28 J2.B30 J2.C4 J2.C7 J2.C10 J2.C13 J2.C16 J2.C17 J2.C18 J2.C19 J2.C20 J2.C25 J2.C30 J2.D4 J2.D7 J2.D10 J2.D13 J2.D16 J2.D20 J2.D25 J2.D30 J2.E5 J2.E6 J2.E7 J2.E10 J2.E16 J2.E20 J2.E22 J2.E25 J2.E28 J2.E29 J7.3 J7.4 J7.9 J15.2 J16.2 J17.2 J18.2 J23.6 J24.5(GND) R21.2 R151.2 R170.1 R218.2 R436.2 U2.2(GND) U8.2(GND) U8.25(PAD) U36.1(GND) U38.4(GND) U63.2(GND) U64.2(GND) ; also on sheet 2 3 4 5 6 7 8 9 10 11 12 13 14 15 16 17 21 22 23 24 25 26 27 28 29 30 39 40
VCC1V8: C212.1 U63.1(IN) U63.3(ON) ; also on sheet 11 12 13 14 15 21 24
VCC1V8_HSE: C18.1 C19.1 C206.1 J2.C2 J2.C3 U63.5(QOD) U63.6(OUT)
VCC3V3_IO_HSE: C14.1 C16.1 C205.1 J2.A27 J2.A28 J2.A29 U64.5(QOD) U64.6(OUT)
VCC_3V3_SYS: C26.1 C29.1 C216.1 J7.10 R19.2 R153.1 U8.5(V+) U64.1(IN) U64.3(ON) ; also on sheet 2 5 6 7 8 10 11 12 13 14 15 16 17 21 23 24 25 26 27 29 30 39 40
VCC_5V0: C15.1 C139.2 FL7.1(I) U2.1(IN) U2.3(ON) ; also on sheet 4 6 17 25
VCC_5V0_HSE: C11.1 C12.1 C13.1 J2.A1 J2.A2 J2.A3 U2.5(QOD) U2.6(OUT)
BOOTMODE0: RA1.8 RA2.1 U23.T20(GPMC0_AD0) ; also on sheet 29
BOOTMODE1: RA1.7 RA2.2 U23.U21(GPMC0_AD1) ; also on sheet 29
BOOTMODE2: RA1.6 RA2.3 U23.T18(GPMC0_AD2) ; also on sheet 29
BOOTMODE3: RA1.5 RA2.4 U23.U20(GPMC0_AD3) ; also on sheet 29
BOOTMODE4: RA1.4 RA2.5 U23.U18(GPMC0_AD4) ; also on sheet 29
BOOTMODE5: RA1.3 RA2.6 U23.U19(GPMC0_AD5) ; also on sheet 29
BOOTMODE6: RA1.2 RA2.7 U23.V20(GPMC0_AD6) ; also on sheet 29
BOOTMODE7: RA1.1 RA2.8 U23.V21(GPMC0_AD7) ; also on sheet 29
BOOTMODE8: RA3.8 RA4.1 U23.V19(GPMC0_AD8) ; also on sheet 29
BOOTMODE9: RA3.7 RA4.2 U23.T17(GPMC0_AD9) ; also on sheet 29
BOOTMODE10: RA3.6 RA4.3 U23.R16(GPMC0_AD10) ; also on sheet 29
BOOTMODE11: RA3.5 RA4.4 U23.W20(GPMC0_AD11) ; also on sheet 29
BOOTMODE12: RA3.4 RA4.5 U23.W21(GPMC0_AD12) ; also on sheet 29
BOOTMODE13: RA3.3 RA4.6 U23.V18(GPMC0_AD13) ; also on sheet 29
BOOTMODE14: RA3.2 RA4.7 U23.Y21(GPMC0_AD14) ; also on sheet 29
BOOTMODE15: RA3.1 RA4.8 U23.Y20(GPMC0_AD15) ; also on sheet 29
CPSW_RGMII1_TD0: U23.V15(PRG1_PRU1_GPO7) ; also on sheet 2
CPSW_RGMII1_TD1: U23.V14(PRG1_PRU1_GPO9) ; also on sheet 2
CPSW_RGMII1_TD2: U23.W14(PRG1_PRU1_GPO10) ; also on sheet 2
CPSW_RGMII1_TD3: U23.AA14(PRG1_PRU1_GPO17) ; also on sheet 2
CPSW_RGMII1_TX_CTL: U23.U15(PRG1_PRU0_GPO9) ; also on sheet 2
CPSW_RGMII1_TXC: U23.U14(PRG1_PRU0_GPO10) ; also on sheet 2
FSI_FET_ENn: R21.1 U8.17(~{EN})
FSI_FET_SEL: R218.1 U8.11(IN2) U8.21(IN1) ; also on sheet 13
FSI_RX0_CLK: J7.2 U8.8(NO1)
FSI_RX0_D0: J7.6 U8.10(NO2)
FSI_RX0_D1: J7.8 U8.12(NO3)
FSI_TX0_CLK: J7.1 U8.13(NO6)
FSI_TX0_D0: J7.5 U8.14(NO4)
FSI_TX0_D1: J7.7 U8.15(NO5)
GPMC0_AD0: J2.E14 RA1.9
GPMC0_AD1: J2.D14 RA1.10
GPMC0_AD2: J2.C14 RA1.11
GPMC0_AD3: J2.E15 RA1.12
GPMC0_AD4: J2.D15 RA1.13
GPMC0_AD5: J2.C15 RA1.14
GPMC0_AD6: J2.E17 RA1.15
GPMC0_AD7: J2.D17 RA1.16
GPMC0_AD8: J2.A22 U8.23(NC1)
GPMC0_AD8/FSI_RX0_CLK: RA3.9 U8.1(COM1)
GPMC0_AD9: J2.A21 U8.22(NC2)
GPMC0_AD9/FSI_RX0_D0: RA3.10 U8.3(COM2)
GPMC0_AD10: J2.B21 U8.20(NC3)
GPMC0_AD10/FSI_RX0_D1: RA3.11 U8.4(COM3)
GPMC0_AD11: J2.E21 RA3.12
GPMC0_AD12: J2.C21 RA3.13
GPMC0_AD13: J2.D21 RA3.14
GPMC0_AD14: J2.B20 U8.18(NC4)
GPMC0_AD14/FSI_TX0_D0: RA3.15 U8.6(COM4)
GPMC0_AD15: J2.A19 U8.16(NC5)
GPMC0_AD15/FSI_TX0_D1: RA3.16 U8.7(COM5)
GPMC0_ADVn_ALE: RA5.7 RA6.2 U23.P16(GPMC0_ADVN_ALE)
GPMC0_BE0n_CLE: RA5.4 RA6.5 U23.P17(GPMC0_BE0N_CLE)
GPMC0_BE1n: RA5.3 RA6.6 U23.T19(GPMC0_BE1N)
GPMC0_CLK: RA5.8 RA6.1 U23.R17(GPMC0_CLK)
GPMC0_CSn0: R390.1 R391.1 U23.R19(GPMC0_CSN0)
GPMC0_CSn1: J2.E19 U23.R20(GPMC0_CSN1)
GPMC0_CSn2: J2.D18 U23.P19(GPMC0_CSN2)
GPMC0_CSn3: J2.D19 U23.R21(GPMC0_CSN3)
GPMC0_DIR: J2.E18 U23.N17(GPMC0_DIR)
GPMC0_OEn_REn: RA5.6 RA6.3 U23.R18(GPMC0_OEN_REN)
GPMC0_WAIT0: RA5.2 RA6.7 U23.W19(GPMC0_WAIT0)
GPMC0_WAIT1: RA5.1 RA6.8 U23.Y18(GPMC0_WAIT1)
GPMC0_WEn: RA5.5 RA6.4 U23.T21(GPMC0_WEN)
GPMC0_WPn: R392.1 R393.1 U23.N16(GPMC0_WPN)
HSE_DETECT: J2.E4 ; also on sheet 10
HSE_GPIO0_31: J2.B22 RA5.9
HSE_GPIO0_32: J2.C22 RA5.10
HSE_GPIO0_33: J2.D22 RA5.11
HSE_GPIO0_34: J2.C23 RA5.12
HSE_GPIO0_35: J2.B24 RA5.13
HSE_GPIO0_36: J2.A20 U8.19(NC6)
HSE_GPIO0_36/FSI_TX0_CLK: RA5.14 U8.9(COM6)
HSE_GPIO0_37: J2.C24 RA5.15
HSE_GPIO0_38: J2.E26 RA5.16
HSE_GPIO0_39: J2.C26 R393.2
HSE_GPIO0_41: J2.D26 R390.2
HSE_MCAN0_RX/UART4_TXD: J2.E24 ; also on sheet 6
HSE_MCAN0_TX/UART4_RXD: J2.D24 ; also on sheet 6
HSE_MCAN1_RX/I2C3_SDA: J2.C29 ; also on sheet 6
HSE_MCAN1_TX/I2C3_SCL: J2.D29 ; also on sheet 6
HSE_PRG0_PRU0_GPO9: J2.D28 ; also on sheet 2
HSE_PRG0_PRU0_GPO10: J2.B29 ; also on sheet 2
HSE_PRG0_PRU1_GPO7: J2.D23 ; also on sheet 2
HSE_PRG0_PRU1_GPO9: J2.E23 ; also on sheet 2
HSE_PRG0_PRU1_GPO10: J2.E27 ; also on sheet 2
HSE_PRG0_PRU1_GPO17: J2.C28 ; also on sheet 2
HSE_PRG0_PRU1_GPO18: J2.D27 ; also on sheet 2
HSE_PRG0_PRU1_GPO19: J2.C27 ; also on sheet 2
MCU_PORz: J2.E30 ; also on sheet 12
MCU_RESETSTATz: J2.E3 ; also on sheet 12
MCU_RESETz: J2.D3 ; also on sheet 12 25
MIPI_TRC_CLK: RA2.16 ; also on sheet 26
MIPI_TRC_CTL: RA2.15 ; also on sheet 26
MIPI_TRC_DAT00: RA2.14 ; also on sheet 26
MIPI_TRC_DAT01: RA2.13 ; also on sheet 26
MIPI_TRC_DAT02: RA2.12 ; also on sheet 26
MIPI_TRC_DAT03: RA2.11 ; also on sheet 26
MIPI_TRC_DAT04: RA2.10 ; also on sheet 26
MIPI_TRC_DAT05: RA2.9 ; also on sheet 26
MIPI_TRC_DAT06: RA4.16 ; also on sheet 26
MIPI_TRC_DAT07: RA4.15 ; also on sheet 26
MIPI_TRC_DAT08: RA4.14 ; also on sheet 26
MIPI_TRC_DAT09: RA4.13 ; also on sheet 26
MIPI_TRC_DAT10: RA4.12 ; also on sheet 26
MIPI_TRC_DAT11: RA4.11 ; also on sheet 26
MIPI_TRC_DAT12: RA4.10 ; also on sheet 26
MIPI_TRC_DAT13: RA4.9 ; also on sheet 26
MIPI_TRC_DAT14: RA6.16 ; also on sheet 26
MIPI_TRC_DAT15: RA6.15 ; also on sheet 26
MIPI_TRC_DAT16: RA6.14 ; also on sheet 26
MIPI_TRC_DAT17: RA6.13 ; also on sheet 26
MIPI_TRC_DAT18: RA6.12 ; also on sheet 26
MIPI_TRC_DAT19: RA6.11 ; also on sheet 26
MIPI_TRC_DAT20: RA6.10 ; also on sheet 26
MIPI_TRC_DAT21: RA6.9 ; also on sheet 26
MIPI_TRC_DAT22: R392.2 ; also on sheet 26
MIPI_TRC_DAT23: R391.2 ; also on sheet 26
PRG0_HSE_ETH1_CLK: J2.A17 ; also on sheet 11
PRG0_HSE_ETH2_CLK: J2.B17 ; also on sheet 11
PRG0_MDIO0_MDC: J2.A5 U23.P3(PRG0_MDIO0_MDC)
PRG0_MDIO0_MDIO: J2.A4 R19.1 U23.P2(PRG0_MDIO0_MDIO)
PRG0_PRU0_GPO9/CPSW_RGMII1_RX_CTL: U23.W6(PRG0_PRU0_GPO9) ; also on sheet 2
PRG0_PRU0_GPO10/CPSW_RGMII1_RXC: U23.AA5(PRG0_PRU0_GPO10) ; also on sheet 2
PRG0_PRU0GPO0: J2.B12 U23.Y1(PRG0_PRU0_GPO0)
PRG0_PRU0GPO1: J2.E8 U23.R4(PRG0_PRU0_GPO1)
PRG0_PRU0GPO2: J2.A8 U23.U2(PRG0_PRU0_GPO2)
PRG0_PRU0GPO3: J2.A9 U23.V2(PRG0_PRU0_GPO3)
PRG0_PRU0GPO4: J2.A13 U23.AA2(PRG0_PRU0_GPO4)
PRG0_PRU0GPO5: J2.C6 U23.R3(PRG0_PRU0_GPO5)
PRG0_PRU0GPO6: J2.D8 U23.T3(PRG0_PRU0_GPO6)
PRG0_PRU0GPO7: J2.B7 U23.T1(PRG0_PRU0_GPO7)
PRG0_PRU0GPO8: J2.A7 U23.T2(PRG0_PRU0_GPO8)
PRG0_PRU0GPO11: J2.B14 U23.Y3(PRG0_PRU0_GPO11)
PRG0_PRU0GPO12: J2.A14 U23.AA3(PRG0_PRU0_GPO12)
PRG0_PRU0GPO13: J2.C5 U23.R6(PRG0_PRU0_GPO13)
PRG0_PRU0GPO14: J2.C9 U23.V4(PRG0_PRU0_GPO14)
PRG0_PRU0GPO15: J2.D12 U23.T5(PRG0_PRU0_GPO15)
PRG0_PRU0GPO16: J2.E9 U23.U4(PRG0_PRU0_GPO16)
PRG0_PRU0GPO17: J2.B8 U23.U1(PRG0_PRU0_GPO17)
PRG0_PRU0GPO18: J2.B9 U23.V1(PRG0_PRU0_GPO18)
PRG0_PRU0GPO19: J2.B11 U23.W1(PRG0_PRU0_GPO19)
PRG0_PRU1_GPO7/CPSW_RGMII1_RD0: U23.W5(PRG0_PRU1_GPO7) ; also on sheet 2
PRG0_PRU1_GPO9/CPSW_RGMII1_RD1: U23.Y5(PRG0_PRU1_GPO9) ; also on sheet 2
PRG0_PRU1_GPO10/CPSW_RGMII1_RD2: U23.V6(PRG0_PRU1_GPO10) ; also on sheet 2
PRG0_PRU1_GPO17/CPSW_RGMII1_RD3: U23.V5(PRG0_PRU1_GPO17) ; also on sheet 2
PRG0_PRU1_GPO18/CPSW_RGMII1_MDIO: TP20.1(TP) U23.P5(PRG0_PRU1_GPO18) ; also on sheet 2
PRG0_PRU1_GPO19/CPSW_RGMII1_MDC: TP64.1(TP) U23.R2(PRG0_PRU1_GPO19) ; also on sheet 2
PRG0_PRU1GPO0: J2.A12 U23.Y2(PRG0_PRU1_GPO0)
PRG0_PRU1GPO1: J2.A11 U23.W2(PRG0_PRU1_GPO1)
PRG0_PRU1GPO2: J2.D9 U23.V3(PRG0_PRU1_GPO2)
PRG0_PRU1GPO3: J2.C8 U23.T4(PRG0_PRU1_GPO3)
PRG0_PRU1GPO4: J2.B13 U23.W3(PRG0_PRU1_GPO4)
PRG0_PRU1GPO5: J2.D6 U23.P4(PRG0_PRU1_GPO5)
PRG0_PRU1GPO6: J2.E11 U23.R5(PRG0_PRU1_GPO6)
PRG0_PRU1GPO8: J2.B4 U23.R1(PRG0_PRU1_GPO8)
PRG0_PRU1GPO11: J2.D11 U23.W4(PRG0_PRU1_GPO11)
PRG0_PRU1GPO12: J2.B15 U23.Y4(PRG0_PRU1_GPO12)
PRG0_PRU1GPO13: J2.D5 U23.T6(PRG0_PRU1_GPO13)
PRG0_PRU1GPO14: J2.E12 U23.U6(PRG0_PRU1_GPO14)
PRG0_PRU1GPO15: J2.C11 U23.U5(PRG0_PRU1_GPO15)
PRG0_PRU1GPO16: J2.A15 U23.AA4(PRG0_PRU1_GPO16)
PRG1_ETH2_LED_1000/RX_ER: U23.AA13(PRG1_PRU1_GPO5) ; also on sheet 39
PRG1_ETH2_LED_LINK: U23.U12(PRG1_PRU1_GPO8) ; also on sheet 39
PRG1_ETH3_LED_1000/RX_ER: U23.V13(PRG1_PRU0_GPO5) ; also on sheet 40
PRG1_ETH3_LED_LINK: U23.W13(PRG1_PRU0_GPO8) ; also on sheet 40
PRG1_IEP0_EDC_LATCH_IN0: J17.1 U23.V7(PRG1_PRU0_GPO18)
PRG1_IEP0_EDC_LATCH_IN1: J15.1 U23.U13(PRG1_PRU0_GPO7)
PRG1_IEP0_EDC_SYNC_OUT0: J18.1 U23.W7(PRG1_PRU0_GPO19)
PRG1_IEP0_EDC_SYNC_OUT2: J16.1 U23.U7(PRG1_PRU0_GPO17)
PRG1_MDIO_MDC: TP21.1(TP) U23.Y6(PRG1_MDIO0_MDC) ; also on sheet 39 40
PRG1_MDIO_MDIO: TP22.1(TP) U23.AA6(PRG1_MDIO0_MDIO) ; also on sheet 39 40
PRG1_PRU1GPO18: J2.E13 U23.Y13(PRG1_PRU1_GPO18)
PRG1_PRU1GPO19: J2.C12 U23.V12(PRG1_PRU1_GPO19)
PRG1_RGMII1_RD0: U23.Y7(PRG1_PRU0_GPO0) ; also on sheet 40
PRG1_RGMII1_RD1: U23.U8(PRG1_PRU0_GPO1) ; also on sheet 40
PRG1_RGMII1_RD2: U23.W8(PRG1_PRU0_GPO2) ; also on sheet 40
PRG1_RGMII1_RD3: U23.V8(PRG1_PRU0_GPO3) ; also on sheet 40
PRG1_RGMII1_RX_CTL: U23.Y8(PRG1_PRU0_GPO4) ; also on sheet 40
PRG1_RGMII1_RXC: U23.AA7(PRG1_PRU0_GPO6) ; also on sheet 40
PRG1_RGMII1_TD0: U23.AA8(PRG1_PRU0_GPO11) ; also on sheet 40
PRG1_RGMII1_TD1: U23.U9(PRG1_PRU0_GPO12) ; also on sheet 40
PRG1_RGMII1_TD2: U23.W9(PRG1_PRU0_GPO13) ; also on sheet 40
PRG1_RGMII1_TD3: U23.AA9(PRG1_PRU0_GPO14) ; also on sheet 40
PRG1_RGMII1_TX_CTL: U23.Y9(PRG1_PRU0_GPO15) ; also on sheet 40
PRG1_RGMII1_TXC: U23.V9(PRG1_PRU0_GPO16) ; also on sheet 40
PRG1_RGMII2_RD0: U23.W11(PRG1_PRU1_GPO0) ; also on sheet 39
PRG1_RGMII2_RD1: U23.V11(PRG1_PRU1_GPO1) ; also on sheet 39
PRG1_RGMII2_RD2: U23.AA12(PRG1_PRU1_GPO2) ; also on sheet 39
PRG1_RGMII2_RD3: U23.Y12(PRG1_PRU1_GPO3) ; also on sheet 39
PRG1_RGMII2_RX_CTL: U23.W12(PRG1_PRU1_GPO4) ; also on sheet 39
PRG1_RGMII2_RXC: U23.U11(PRG1_PRU1_GPO6) ; also on sheet 39
PRG1_RGMII2_TD0: U23.AA10(PRG1_PRU1_GPO11) ; also on sheet 39
PRG1_RGMII2_TD1: U23.V10(PRG1_PRU1_GPO12) ; also on sheet 39
PRG1_RGMII2_TD2: U23.U10(PRG1_PRU1_GPO13) ; also on sheet 39
PRG1_RGMII2_TD3: U23.AA11(PRG1_PRU1_GPO14) ; also on sheet 39
PRG1_RGMII2_TX_CTL: U23.Y11(PRG1_PRU1_GPO15) ; also on sheet 39
PRG1_RGMII2_TXC: U23.Y10(PRG1_PRU1_GPO16) ; also on sheet 39
SoC_I2C0_SCL: J2.E1 ; also on sheet 6 10 13
SoC_I2C0_SDA: J2.E2 ; also on sheet 6 10 13
SOC_SPI1_CLK: J2.C1 ; also on sheet 6
SOC_SPI1_CS0: J2.D1 ; also on sheet 6
SOC_SPI1_CS1: J2.D2 ; also on sheet 6
SOC_SPI1_MISO: J2.B1 ; also on sheet 6
SOC_SPI1_MOSI: J2.B2 ; also on sheet 6
SoC_USB0_VBUS: R427.2 R436.1 U23.T14(USB0_VBUS)
USB0_AB_DM: FL22.4 J24.2(D-) U38.1(D+)
USB0_AB_DP: FL22.3 J24.3(D+) U38.2(D-)
USB0_AB_ID: J23.5 J24.4(ID) U23.U16(USB0_ID) U38.3(ID)
USB0_DM: FL22.1 U23.AA20(USB0_DM)
USB0_DP: FL22.2 U23.AA19(USB0_DP)
USB0_DRVBUS: R151.1 U23.E19(USB0_DRVVBUS) U36.4(EN)
USB0_RCALIB: TP67.1(TP) U23.U17(USB0_RCALIB)
USB0_VBUS: C140.1 J23.1 J24.1(VCC) R428.1 U36.6(OUT1) U36.7(OUT2) U36.8(OUT3) U38.6(VBUS)
USB1_SHIELD: C153.2 J24.6(SH1) J24.7(SH2) J24.8(SH3) J24.9(SH4) J24.10(SH5) R170.2
N17839730: C143.1 J23.2
N18968753: C141.1 FL7.3(O) U36.2(IN1) U36.3(IN2)
N18968782: R153.2 U36.5(~{OC})
N19312123: D7.3(C) R427.1 R428.2

Not connected (* = marked no-connect by the designer): D7 2(NC)*; J2 A26* A30*; J23 3* 4*; U2 4(NC)*; U8 24(N.C.)*; U38 5(NC)*; U63 4(NC)*; U64 4(NC)*

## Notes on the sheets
sheet 18
- Off Page Connections
- SYNC TP
- PRG0 & PRG1
- To Presence
  Detect Buffer
- From Processor GPMC
- From FSI mux
- From Processor GPMC
  resistor muxed
  with MIPI
- From Processor
- From clock Buffer
- HIGH SPEED EXPANSION CONNECTOR
- To and from ICSSG1
  RGMII 2
  Ethernet PHY
- To and from ICSSG2
  RGMII 1
  Ethernet PHY
- From MUX
  To HSE
- HSE CONNECTOR LOAD SWITCHES
- To MUX
  From SoC
- 5V@1.5A
- 3.3V@1.5A
- 1.8V@1.5A
- From CPSW
  RGMII 1 PHY
sheet 19
- 0- Ohm Res MUX between HSE Connector and TRACE Functionality
  -For HSE Connector  RA1 , RA3 , RA5  , R393 & R390 Should be installed and  RA2, RA4 ,RA6 , R391& R392 Should be DNI'd.
  -For TRACE  RA2, RA4 ,RA6 , R391& R392  Should be Installed and    RA1 , RA3 , RA5  , R393 & R390  Should be DNI'd.
- GPMC
- To HSE
- To Boot Mode Buffer ,
  HSE & MIPI Conn
- To MIPI Connector
- To FSI Mux & HSE
- To MIPI Connector
- To HSE  & FSI Mux
- To MIPI Connector
- GPMC TO FSI & HSE CONNECTOR
- FSI CONNECTOR
- To HSE CON
- To MIPI Connector
- FSI_FET_SEL
  fromIO
  Expander
- Off Page Connections
- TS3A27518ERTWR Truth Table
- From IO Expander
- NC1/2/3 TO
  COM1/2/3 &
  COM1/2/3 TO
  NC1/2/3
- NC4/5/6 TO
  COM14/5/6 &
  COM4/5/6 TO
  NC4/5/6
- NO1/2/3 TO
  COM1/2/3 &
  COM1/2/3 TO
  NO1/2/3
- NO4/5/6 TO
  COM14/5/6 &
  COM4/5/6 TO
  NO4/5/6
- EN#
- IN1
- IN2
- To HSE Connector
- H
- X
- X
- OFF
- OFF
- OFF
- OFF
- From FSI mux
  To HSE Connector
- L
- L
- L
- ON
- ON
- OFF
- OFF
- L
- H
- L
- OFF
- ON
- ON
- OFF
- L
- L
- H
- ON
- OFF
- OFF
- ON
- L
- H
- H
- OFF
- OFF
- ON
- ON
- It should be connected to PORz of the SoC TBD
sheet 20
- USB 2.0 INTERFACE
- 5V Power switch for slave
- 2X3 header to enable bulk capacitance on USB0_VBUS in host mode and
  to ground USB0_AB_ID pin, if a non standard cable is used
- Feed through Cap
- 5V@500mA
- Micro USB 2.0 AB Connector
- Resistor divider on SOC_VBUS
